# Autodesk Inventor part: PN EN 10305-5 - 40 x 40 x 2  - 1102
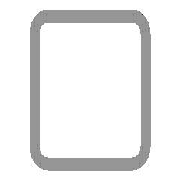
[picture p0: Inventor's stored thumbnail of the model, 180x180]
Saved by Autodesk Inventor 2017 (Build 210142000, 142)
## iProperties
_CCFamilyMember: 26
_CCFamilyDisplayName: PN EN 10305-5 (Rury kwadratowe, spawane, wymiarowane na zimno) - Rury stalowe do zastosowań precyzyjnych -  (Część 5: Rury kwadratowe, spawane, wymiarowane na z
_FrameMemberDoc: Frame Member File
_Version: 15.0.0
_GetPNFromCC: 1
Created: 2016-02
Part Number: PN EN 10305-5 - 40 x 40 x 2  - 1102
Material: Stal, miękka
Description: Rury stalowe do zastosowań precyzyjnych -  (Część 5: Rury kwadratowe, spawane, wymiarowane na zimno)
Document SubType Name: Modeling
Standard: PN
Designer: X
Standards Organization: PN
Language: pl-PL
Size Designation: 40 x 40 x 2
Categories: <MemberInstance><Categories><Category DisplayName="Kształtowniki konstrukcyjne" InternalName="089c4875-fa83-4c05-b084-43b9cc11f5ed" Mnemonic="GRDR"><CategoryPar
Stock Number: 40 x 40 x 2
Density: 7.85 g/cm^3
Appearance: Częściowo polerowana
IsCustomPart: 1
G_L: 1102,000 mm
G_W: 40,000 mm
G_H: 40,000 mm
Author: X
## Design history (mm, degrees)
node "Płaszczyzna początkowa"
node "Płaszczyzna końcowa"
sketch "Szkic"
  geometry: L1 (-20, -17)-(-20, 17); L2 (-17, 20)-(17, 20); L3 (20, 17)-(20, -17); L4 (17, -20)-(-17, -20); L5 (-17, 18)-(17, 18); L6 (18, 17)-(18, -17); L7 (17, -18)-(-17, -18); L8 (-18, -17)-(-18, 17); L9 (0, 28.87)-(0, -28.87) reference; L10 (-28.87, 0)-(28.87, 0) reference; A1 r 3 centre (-17, -17) between (-20, -17) and (-17, -20); A2 r 3 centre (-17, 17) between (-17, 20) and (-20, 17); A3 r 3 centre (17, 17) between (20, 17) and (17, 20); A4 r 3 centre (17, -17) between (17, -20) and (20, -17); A5 r 1 centre (-17, 17) between (-17, 18) and (-18, 17); A6 r 1 centre (17, 17) between (18, 17) and (17, 18); A7 r 1 centre (17, -17) between (17, -18) and (18, -17); A8 r 1 centre (-17, -17) between (-18, -17) and (-17, -18)
  constraints: 16 end point, 16 point on circle, 8 centre point, 8 tangent, 4 parallel, 3 equal radius, 2 perpendicular, 7 other
  dimensions: "d7" = 3 radius of A1 (= G_IR); "d10" = 40 distance between parallel lines of L2 L4 (= G_H); "d11" = 40 distance between parallel lines of L1 L3 (= G_W); "d12" = 2 distance between parallel lines of L3 L6 (= G_T); "d15" = 20 distance between parallel lines of L2 L10 (= 0.5 x d10); "d16" = 20 distance between parallel lines of L9 L3 (= 0.5 x d11)
extrude "Bryła" new body sketch "Szkic" stored distance "d3" = 1102 (= G_L); taper "d4" = 0 deg
node "Driven Length"
  sketch "Sketch3"
    geometry: L1 (0, 0)-(10, 0) reference
    constraints: 2 end point, 1 horizontal
  workplane "Work Plane3"
  sketch "Sketch4"
    geometry: L1 (-2, 0)-(12, 0) reference; L2 (-2, 1102)-(12, 1102) reference
    dimensions: "d18" = 1102 distance between parallel lines of L1 L2 (derived)
body "Solid1"
other parameters: "G_W" = 40 [user parameter; used in 1 equation term], "G_H" = 40 [user parameter; used in 1 equation term], "G_T" = 2 [user parameter; used in 1 equation term], "G_IR" = 3 [user parameter; used in 1 equation term], "G_L" = 1102 (= d18) [user parameter; used in 1 equation term], "G_OFFSET_START" = 0 [user parameter; used in 1 equation term], "G_OFFSET_END" = -38 [user parameter; used in 1 equation term], "d13" = 0 (computed from G_OFFSET_START), "d14" = 1102 (= G_OFFSET_END + B_L), "d17" = 90 deg
